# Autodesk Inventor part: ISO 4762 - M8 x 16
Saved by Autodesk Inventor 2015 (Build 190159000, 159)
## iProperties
Created: 2014-02
Part Number: ISO 4762 - M8 x 16
Material: Nerezová ocel 440C
Description: Šroub s válcovou hlavou s vnitřním šestihranem
Document SubType Name: Modeling
Standard: ISO 4762
Designer: navara
Standard Revision: Fourth edition 2004-03-01
Standards Organization: ISO
Language: cs-CZ
Size Designation: M8 x 16
Categories: <MemberInstance><Categories><Category DisplayName="Spojovací materiál" InternalName="e4da775c-781d-43d5-af7c-5136215cf5a6" Mnemonic="FSTN"><Category DisplayName
Density: 7.75 g/cm^3
Appearance: Pololeštěná
IsCustomPart: 0
Author: navara
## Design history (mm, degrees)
feature "Base1"
node "Těleso1"
